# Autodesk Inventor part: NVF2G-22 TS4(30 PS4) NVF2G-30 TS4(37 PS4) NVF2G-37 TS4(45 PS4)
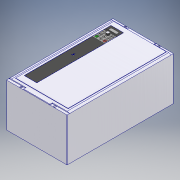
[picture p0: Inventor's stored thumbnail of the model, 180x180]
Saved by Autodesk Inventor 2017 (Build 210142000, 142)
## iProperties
Part Number: NVF2G-22 TS4(30 PS4) NVF2G-30 TS4(37 PS4) NVF2G-37 TS4(45 PS4)
Material: Типовые
Document SubType Name: Modeling
Designer: RSagdiev
Density: 1 g/cm^3
Appearance: По умолчанию
Author: RSagdiev
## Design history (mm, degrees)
sketch "Эскиз1"
  geometry: L1 (0, 0)-(44.679, 0) reference; L2 (0, 0)-(0, 56.035) reference; L3 (0, 0)-(527, 0); L4 (527, 0)-(527, 214.6); L5 (527, 214.6)-(0, 214.6); L6 (0, 214.6)-(0, 0)
  constraints: 12 end point, 3 horizontal, 2 parallel, 2 vertical, 1 perpendicular
  dimensions: "d0" = 527 distance of L5.end L4.end; "d1" = 214.6 distance of L4.end L3.end
extrude "Выдавливание1" new body sketch "Эскиз1" stored distance "d2" = 300; taper "d3" = 0 deg
sketch "Эскиз2"
  geometry: L1 (0, 0)-(0, 527) reference; L2 (300, 0)-(300, 527) reference; L3 (0, 527)-(85, 527); L4 (300, 527)-(300, 515); L5 (300, 0)-(215, 0); L6 (0, 0)-(0, 12); L7 (0, 527)-(300, 527) reference; L8 (0, 527)-(85, 527); L9 (85, 527)-(85, 515); L10 (85, 515)-(0, 515); L11 (0, 515)-(0, 527); L12 (300, 527)-(215, 527); L13 (215, 527)-(215, 515); L14 (215, 515)-(300, 515); L15 (300, 515)-(300, 527); L16 (0, 0)-(300, 0) reference; L17 (0, 0)-(85, 0); L18 (85, 0)-(85, 12); L19 (85, 12)-(0, 12); L20 (0, 12)-(0, 0); L21 (300, 0)-(215, 0); L22 (215, 0)-(215, 12); L23 (215, 12)-(300, 12); L24 (300, 12)-(300, 0); L25 (85, 527)-(215, 527); L26 (0, 515)-(0, 527); L27 (215, 527)-(300, 527); L28 (300, 515)-(300, 12); L29 (215, 0)-(85, 0); L30 (300, 12)-(300, 0); L31 (85, 0)-(0, 0); L32 (0, 12)-(0, 515); 1 further point
  constraints: 56 end point, 26 parallel, 13 perpendicular, 7 horizontal
  dimensions: "d4" = 85 distance of L9.end L10.end; "d5" = 12 distance of L3.end L9.end; "d6" = 85 distance of L4.end L13.end; "d7" = 12 distance of L13.end L12.end; "d8" = 85 distance of L6.end L18.end; "d9" = 12 distance of L18.end L17.end; "d10" = 85 distance of L22.end L23.end; "d11" = 12 distance of L5.end L22.end
extrude "Выдавливание2" new body sketch "Эскиз2" distance "d12" = 4; taper "d13" = 0 deg
chamfer "Фаска1" distance "d14" = 4; stored, may be unused: second distance "d15" = 2, angle "d16" = 45 deg
sketch "Эскиз3"
  geometry: L1 (280, 25)-(280, 511); L2 (20, 511)-(280, 511); L3 (20, 511)-(20, 25); L4 (20, 511)-(280, 511); L5 (20, 25)-(280, 25); L6 (85, 523)-(215, 523) reference; L7 (85, 0)-(215, 0) reference; L8 (0, 515)-(0, 12) reference; L9 (300, 12)-(300, 515) reference; 1 further point
  constraints: 11 end point, 2 perpendicular, 1 horizontal
  dimensions: "d160" = 12 distance between parallel lines of L4 L6; "d161" = 25 distance between parallel lines of L7 L5; "d162" = 20 distance between parallel lines of L8 L3 (derived); "d164" = 20 distance between parallel lines of L9 L1
extrude "Выдавливание3" new body sketch "Эскиз3" distance "d17" = 2; taper "d18" = 0 deg
sketch "Эскиз4"
  geometry: L1 (91, 487)-(32, 487); L2 (30, 485)-(30, 59); L3 (32, 57)-(91, 57); L4 (93, 59)-(93, 485); L5 (0, 527)-(300, 527) reference; L6 (0, 515)-(0, 12) reference; A1 r 2 centre (32, 485) between (32, 487) and (30, 485); A2 r 2 centre (91, 485) between (93, 485) and (91, 487); A3 r 2 centre (91, 59) between (91, 57) and (93, 59); A4 r 2 centre (32, 59) between (30, 59) and (32, 57); 6 further points
  constraints: 8 end point, 8 point on circle, 8 tangent, 6 point on line, 4 centre point, 3 equal radius, 2 parallel, 1 horizontal, 1 perpendicular
  dimensions: "d20" = 63 distance of point (93, 57) point (30, 57); "d21" = 430 distance of point (30, 57) point (30, 487); "d24" = 2 radius of A1; "d165" = 40 distance between parallel lines of L5 L1; "d166" = 30 distance between parallel lines of L6 L2
extrude "Выдавливание4" cut sketch "Эскиз4" distance "d25" = 0.6; taper "d26" = 0 deg
sketch "Эскиз5"
  geometry: L1 (0, 527)-(300, 527) reference; L2 (0, 0)-(0, 527) reference; L3 (300, 527)-(300, 0) reference; L4 (0, 0)-(300, 0) reference; C1 r 5 at (66.7, 521); C2 r 5 at (233.3, 521); C3 r 5 at (66.7, 6); C4 r 5 at (233.3, 6); 1 further point
  constraints: 4 centre point
  dimensions: "d27" = 10 diameter of C1; "d28" = 6 distance from line of C1.centre L1; "d30" = 10 diameter of C2; "d31" = 6 distance from line of C2.centre L1; "d33" = 10 diameter of C3; "d34" = 6 distance from line of L4 C3.centre; "d36" = 10 diameter of C4; "d38" = 6 distance from line of C4.centre L4; "d169" = 166.6 distance of C1.centre C2.centre; "d170" = 66.7 distance from line of L3 C2.centre; "d172" = 166.6 distance of C4.centre C3.centre (derived); "d173" = 66.7 distance from line of L3 C4.centre (derived); "d202" = 66.7 distance from line of L2 C1.centre (derived)
extrude "Выдавливание5" cut sketch "Эскиз5" stored distance "d39" = 0.6; taper "d40" = 0 deg
sketch "Эскиз6"
  geometry: L1 (30, 396)-(30, 452); L2 (91, 394)-(32, 394); L3 (93, 485)-(93, 452); L4 (32, 487)-(91, 487); L5 (30, 396)-(30, 485); L6 (30, 452)-(93, 452); L7 (93, 485)-(93, 452); L8 (30, 452)-(30, 485); L9 (93, 452)-(93, 396); L10 (43.5, 463)-(79.5, 463); L11 (81.5, 465)-(81.5, 475); L12 (79.5, 477)-(43.5, 477); L13 (41.5, 475)-(41.5, 465); L14 (41.5, 463)-(81.5, 477); L15 (81.5, 463)-(41.5, 477); L16 (61.5, 440.5)-(61.5, 405.857); L17 (53.25, 440.5)-(53.25, 405.857); L18 (69.75, 405.857)-(69.75, 440.5); L19 (47, 447)-(36, 447); L20 (35, 446)-(35, 435); L21 (36, 434)-(47, 434); L22 (48, 435)-(48, 446); L23 (48, 447)-(35, 434); L24 (35, 447)-(48, 434); L25 (81.5, 465)-(81.5, 400.5); L26 (41.5, 440.5)-(88.409, 440.5); L27 (39.654, 423.179)-(85.729, 423.179); L28 (39.654, 405.857)-(84.963, 405.857); L29 (88, 435)-(88, 446); L30 (76, 434)-(87, 434); L31 (88, 447)-(75, 434); L32 (75, 447)-(88, 434); L33 (75, 446)-(75, 435); L34 (87, 447)-(76, 447); L35 (88, 417.679)-(88, 428.679); L36 (76, 416.679)-(87, 416.679); L37 (88, 429.679)-(75, 416.679); L38 (75, 429.679)-(88, 416.679); L39 (75, 428.679)-(75, 417.679); L40 (87, 429.679)-(76, 429.679); L41 (88, 400.357)-(88, 411.357); L42 (76, 399.357)-(87, 399.357); L43 (88, 412.357)-(75, 399.357); L44 (75, 412.357)-(88, 399.357); L45 (75, 411.357)-(75, 400.357); L46 (87, 412.357)-(76, 412.357); L47 (48, 400.357)-(48, 411.357); L48 (36, 399.357)-(47, 399.357); L49 (48, 412.357)-(35, 399.357); L50 (35, 412.357)-(48, 399.357); L51 (35, 411.357)-(35, 400.357); L52 (47, 412.357)-(36, 412.357); L53 (48, 417.679)-(48, 428.679); L54 (36, 416.679)-(47, 416.679); L55 (48, 429.679)-(35, 416.679); L56 (35, 429.679)-(48, 416.679); L57 (35, 428.679)-(35, 417.679); L58 (47, 429.679)-(36, 429.679); L59 (91, 394)-(32, 394); L60 (0, 527)-(300, 527) reference; L61 (0, 513)-(0, 14); L62 (93, 452)-(93, 396); C1 r 6.5 at (61.5, 440.5); C2 r 6.5 at (61.5, 405.857); C3 r 6.5 at (61.5, 423.179); A1 r 2 centre (43.5, 475) between (43.5, 477) and (41.5, 475); A2 r 2 centre (79.5, 475) between (81.5, 475) and (79.5, 477); A3 r 2 centre (79.5, 465) between (79.5, 463) and (81.5, 465); A4 r 2 centre (43.5, 465) between (41.5, 465) and (43.5, 463); A5 r 8.25 centre (61.5, 440.5) between (69.75, 440.5) and (53.25, 440.5); A6 r 8.25 centre (61.5, 405.857) between (53.25, 405.857) and (69.75, 405.857); A7 r 1 centre (47, 446) between (48, 446) and (47, 447); A8 r 1 centre (47, 435) between (47, 434) and (48, 435); A9 r 1 centre (36, 435) between (35, 435) and (36, 434); A10 r 1 centre (36, 446) between (36, 447) and (35, 446); A11 r 1 centre (87, 435) between (87, 434) and (88, 435); A12 r 1 centre (87, 446) between (88, 446) and (87, 447); A13 r 1 centre (76, 446) between (76, 447) and (75, 446); A14 r 1 centre (76, 435) between (75, 435) and (76, 434); A15 r 1 centre (87, 417.679) between (87, 416.679) and (88, 417.679); A16 r 1 centre (87, 428.679) between (88, 428.679) and (87, 429.679); A17 r 1 centre (76, 428.679) between (76, 429.679) and (75, 428.679); A18 r 1 centre (76, 417.679) between (75, 417.679) and (76, 416.679); A19 r 1 centre (87, 400.357) between (87, 399.357) and (88, 400.357); A20 r 1 centre (87, 411.357) between (88, 411.357) and (87, 412.357); A21 r 1 centre (76, 411.357) between (76, 412.357) and (75, 411.357); A22 r 1 centre (76, 400.357) between (75, 400.357) and (76, 399.357); A23 r 1 centre (47, 400.357) between (47, 399.357) and (48, 400.357); A24 r 1 centre (47, 411.357) between (48, 411.357) and (47, 412.357); A25 r 1 centre (36, 411.357) between (36, 412.357) and (35, 411.357); A26 r 1 centre (36, 400.357) between (35, 400.357) and (36, 399.357); A27 r 1 centre (47, 417.679) between (47, 416.679) and (48, 417.679); A28 r 1 centre (47, 428.679) between (48, 428.679) and (47, 429.679); A29 r 1 centre (36, 428.679) between (36, 429.679) and (35, 428.679); A30 r 1 centre (36, 417.679) between (35, 417.679) and (36, 416.679); A31 r 2 centre (32, 485) between (32, 487) and (30, 485); A32 r 2 centre (91, 485) between (93, 485) and (91, 487); A33 r 2 centre (91, 396) between (91, 394) and (93, 396); A34 r 2 centre (32, 396) between (30, 396) and (32, 394); 15 further points
  constraints: 124 end point, 70 tangent, 68 point on circle, 67 point on line, 37 centre point, 21 equal radius, 15 midpoint, 15 parallel, 11 horizontal, 7 collinear, 7 perpendicular, 3 coincident, 2 vertical
  dimensions: "d43" = 35 distance between parallel lines of L4 L6; "d44" = 40 distance of L15.end L14.end; "d45" = 14 distance of L14.end L15.start; "d46" = 10 distance between parallel lines of L4 L12; "d47" = 2 radius of A1; "d48" = 11.5 distance between parallel lines of L8 L13; "d49" = 16.5 diameter of A6; "d50" = 31.5 distance between parallel lines of L1 L16; "d51" = 11.5 distance from line of L6 L16.start; "d52" = 11.85714 distance from line of L2 L16.end; "d53" = 13 diameter of C1; "d54" = 13 diameter of C2; "d55" = 13 diameter of C3; "d56" = 13 distance of L24.end L23.end; "d57" = 13 distance of L23.end L24.start; "d58" = 1 radius of A7 (derived); "d59" = 11.5 distance from line of L6 L26.start; "d60" = 11.5 distance from line of L5 L26.start; "d61" = 13 distance of L32.end L31.end; "d62" = 13 distance of L31.end L32.start; "d63" = 1 radius of A12 (derived); "d64" = 13 distance of L38.end L37.end; "d65" = 13 distance of L37.end L38.start; "d66" = 1 radius of A16 (derived); "d67" = 13 distance of L44.end L43.end; "d68" = 13 distance of L43.end L44.start; "d69" = 1 radius of A20 (derived); "d70" = 13 distance of L50.end L49.end; "d71" = 13 distance of L49.end L50.start; "d72" = 1 radius of A24 (derived); "d73" = 13 distance of L56.end L55.end; "d74" = 13 distance of L55.end L56.start; "d75" = 1 radius of A28 (derived); "d146" = 40 distance of point (81.5, 440.5) L26.start; "d147" = 4.32143 distance between parallel lines of L40 L30; "d148" = 4.32143 distance between parallel lines of L46 L36; "d149" = 93 distance between parallel lines of L2 L4; "d151" = 2 radius of A31; "d152" = 2 radius of A32; "d153" = 2 radius of A33; "d154" = 2 radius of A34; "d167" = 40 distance between parallel lines of L4 L60 (derived); "d168" = 30 distance between parallel lines of L61 L5 (derived)
extrude "Выдавливание6" new body sketch "Эскиз6" distance "d76" = 0.3; taper "d77" = 0 deg
extrude "Выдавливание7" new body sketch "Эскиз6" distance "d78" = 0.6; taper "d79" = 0 deg
sketch "Эскиз7"
  geometry: L1 (30, 452)-(93, 452) reference; L2 (30, 452)-(93, 452); L3 (93, 452)-(93, 452.1); L4 (93, 452.1)-(30, 452.1); L5 (30, 452.1)-(30, 452); 4 further points; 1 other entity
  constraints: 8 end point, 2 parallel, 1 horizontal, 1 perpendicular, 2 other
  dimensions: "d80" = 0.1 distance of L3.end L2.end
extrude "Выдавливание8" cut sketch "Эскиз7" distance "d81" = 0.3; taper "d82" = 0 deg
sketch "Эскиз8" dims "d91" = 10
  geometry: L1 (30, 452.1)-(93, 452.1) reference; C1 r 1 at (38, 457.1); C2 r 1 at (45.75, 457.1); C3 r 1 at (53.5, 457.1); C4 r 1 at (61.25, 457.1); C5 r 1 at (69, 457.1); C6 r 1 at (76.75, 457.1); C7 r 1 at (84.5, 457.1); 4 further points; 1 other entity
  constraints: 7 centre point, 1 horizontal, 13 other
  dimensions: "d83" = 2 diameter of C1; "d84" = 5 distance from line of C1.centre L1; "d85" = 8 dimension on C1.centre; "d88" = 7.75 distance of C1.centre C2.centre
extrude "Выдавливание9" join sketch "Эскиз8" distance "d93" = 0.3; taper "d94" = 0 deg
sketch "Эскиз9"
  geometry: C1 r 6.5 at (0, 0) reference; C2 r 7.5 at (0, 0); 1 further point
  constraints: 1 centre point, 1 coincident
  dimensions: "d95" = 15 diameter of C2
extrude "Выдавливание10" join sketch "Эскиз9" distance "d96" = 9.4; taper "d97" = -3 deg
sketch "Эскиз10"
  geometry: L1 (0, 7.331)-(0.619, 6.259); L2 (0.619, 6.259)-(-0.619, 6.259); L3 (-0.619, 6.259)-(0, 7.331); 2 further points
  constraints: 6 end point, 7 other
sketch "Эскиз11"
  geometry: L1 (0, 7.917)-(0.884, 6.386); L2 (0.884, 6.386)-(-0.884, 6.386); L3 (-0.884, 6.386)-(0, 7.917); 2 further points
  constraints: 6 end point, 7 other
feature "Лофт1" sketch "Эскиз10", "Эскиз11" dims "d98" = 0, "d99" = 90 deg, "d100" = 0, "d101" = 90 deg
sketch "Эскиз12"
  geometry: L1 (38.019, 442.615)-(44.239, 442.615); L2 (44.239, 442.615)-(44.239, 439.115); L3 (44.239, 439.115)-(38.019, 439.115); L4 (38.019, 439.115)-(38.019, 442.615); L5 (37.069, 425.516)-(45.924, 425.516); L6 (45.924, 425.516)-(45.924, 421.886); L7 (45.924, 421.886)-(37.069, 421.886); L8 (37.069, 421.886)-(37.069, 425.516); L9 (36.713, 408.18)-(46.07, 408.18); L10 (46.07, 408.18)-(46.07, 404.606); L11 (46.07, 404.606)-(36.713, 404.606); L12 (36.713, 404.606)-(36.713, 408.18); L13 (75.542, 408.18)-(87.094, 408.18); L14 (87.094, 408.18)-(87.094, 404.533); L15 (87.094, 404.533)-(75.542, 404.533); L16 (75.542, 404.533)-(75.542, 408.18); L17 (77.323, 425.398)-(85.517, 425.398); L18 (85.517, 425.398)-(85.517, 421.773); L19 (85.517, 421.773)-(77.323, 421.773); L20 (77.323, 421.773)-(77.323, 425.398); L21 (75.423, 442.734)-(88.473, 442.734); L22 (88.473, 442.734)-(88.473, 439.109); L23 (88.473, 439.109)-(75.423, 439.109); L24 (75.423, 439.109)-(75.423, 442.734); 1 further point
  constraints: 12 other
feature "Рельеф1" dims "d105" = 0.1, "d106" = 0
feature "Рельеф2" dims "d107" = 0.1, "d108" = 0
feature "Рельеф3" dims "d109" = 0.1, "d110" = 0
feature "Рельеф4" dims "d111" = 0.1, "d112" = 0
feature "Рельеф5" dims "d113" = 0.1, "d114" = 0
feature "Рельеф6" dims "d115" = 0.1, "d116" = 0
sketch "Эскиз13"
  geometry: L1 (-3.144, -2.347)-(-0.04, 3.728); L2 (-0.04, 3.728)-(3.298, -2.347); L3 (3.298, -2.347)-(2.096, -2.347); L4 (2.096, -2.347)-(-0.04, 1.541); L5 (-0.04, 1.541)-(-2.027, -2.347); L6 (-2.027, -2.347)-(-3.144, -2.347); L7 (-9.387, -8.657)-(8.031, -8.657); L8 (-3.144, -14.967)-(-0.04, -21.041); L9 (-0.04, -21.041)-(3.298, -14.967); L10 (3.298, -14.967)-(2.096, -14.967); L11 (2.096, -14.967)-(-0.04, -18.855); L12 (-0.04, -18.855)-(-2.027, -14.967); L13 (-2.027, -14.967)-(-3.144, -14.967); 1 further point
  constraints: 26 end point, 6 symmetric about line, 2 horizontal, 2 parallel, 2 point on line, 1 collinear
feature "Рельеф7" dims "d117" = 0.1, "d118" = 0
feature "Рельеф8" dims "d119" = 0.1, "d120" = 0
sketch "Эскиз14"
  geometry: L1 (62.079, 278.98)-(70.375, 264.61); L2 (70.375, 264.61)-(53.782, 264.61); L3 (53.782, 264.61)-(62.079, 278.98); L4 (68.948, 265.434)-(62.079, 277.332); L5 (62.079, 277.332)-(55.209, 265.434); L6 (55.209, 265.434)-(68.948, 265.434); L7 (61.252, 273.665)-(60.311, 269.855); L8 (60.311, 269.855)-(62.732, 270.025); L9 (62.732, 270.025)-(61.691, 267.709); L10 (61.691, 267.709)-(60.742, 268.135); L11 (60.742, 268.135)-(60.898, 265.905); L12 (60.898, 265.905)-(63.368, 266.954); L13 (63.368, 266.954)-(62.687, 267.261); L14 (62.687, 267.261)-(64.617, 270.896); L15 (64.617, 270.896)-(61.462, 270.713); L16 (61.462, 270.713)-(63.028, 273.665); L17 (63.028, 273.665)-(61.252, 273.665); 2 further points
  constraints: 34 end point, 2 perpendicular, 2 point on line, 1 parallel, 9 other
extrude "Выдавливание11" cut sketch "Эскиз14" distance "d121" = 0.8; taper "d122" = 0 deg
extrude "Выдавливание12" join sketch "Эскиз14" stored distance "d123" = 0.05; taper "d124" = 0 deg
sketch "Эскиз15"
  geometry: L1 (32.937, 461.659)-(59.334, 461.659); L2 (59.334, 461.659)-(59.334, 458.81); L3 (59.334, 458.81)-(32.937, 458.81); L4 (32.937, 458.81)-(32.937, 461.659); L5 (58.162, 460.617)-(88.881, 460.617); L6 (88.881, 460.617)-(88.881, 456.704); L7 (88.881, 456.704)-(58.162, 456.704); L8 (58.162, 456.704)-(58.162, 460.617); L9 (30, 452.1)-(93, 452.1) reference; C1 r 1 at (38, 457.1) reference; 7 further points; 2 other entities
  constraints: 6 other
  dimensions: "d155" = 0.71019 distance edge to line of C1 L3; "d156" = 2.93695 dimension on L4; "d157" = 4.60387 distance between parallel lines of L9 L7; "d158" = 4.11868 dimension on L6
feature "Рельеф9" sketch "Эскиз15" dims "d125" = 0.1, "d126" = 0
sketch "Эскиз17"
  geometry: L1 (54.534, 359)-(54.534, 352.001); L2 (54.534, 352.001)-(52.465, 352.001); L3 (52.465, 352.001)-(52.465, 359); L4 (52.465, 359)-(54.534, 359); 1 further point
  constraints: 2 other
feature "Рельеф10" sketch "Эскиз17" dims "d144" = 0.1, "d145" = 0
sketch "Эскиз19" dims "d179" = 10
  geometry: L1 (113.24, 333.958)-(134.375, 351.485); L2 (114.525, 332.409)-(135.66, 349.935); L3 (133.09, 353.034)-(111.955, 335.508); L4 (214.6, 515)-(214.6, 12) reference; L5 (113.24, 323.958)-(134.375, 341.485); L6 (114.525, 322.409)-(135.66, 339.935); L7 (133.09, 343.034)-(111.955, 325.508); L8 (113.24, 313.958)-(134.375, 331.485); L9 (114.525, 312.409)-(135.66, 329.935); L10 (133.09, 333.034)-(111.955, 315.508); L11 (113.24, 303.958)-(134.375, 321.485); L12 (114.525, 302.409)-(135.66, 319.935); L13 (133.09, 323.034)-(111.955, 305.508); L14 (113.24, 293.958)-(134.375, 311.485); L15 (114.525, 292.409)-(135.66, 309.935); L16 (133.09, 313.034)-(111.955, 295.508); L17 (113.24, 283.958)-(134.375, 301.485); L18 (114.525, 282.409)-(135.66, 299.935); L19 (133.09, 303.034)-(111.955, 285.508); L20 (113.24, 273.958)-(134.375, 291.485); L21 (114.525, 272.409)-(135.66, 289.935); L22 (133.09, 293.034)-(111.955, 275.508); L23 (113.24, 263.958)-(134.375, 281.485); L24 (114.525, 262.409)-(135.66, 279.935); L25 (133.09, 283.034)-(111.955, 265.508); L26 (113.24, 253.958)-(134.375, 271.485); L27 (114.525, 252.409)-(135.66, 269.935); L28 (133.09, 273.034)-(111.955, 255.508); L29 (113.24, 243.958)-(134.375, 261.485); L30 (114.525, 242.409)-(135.66, 259.935); L31 (133.09, 263.034)-(111.955, 245.508); A1 r 2.013 centre (113.24, 333.958) between (111.955, 335.508) and (114.525, 332.409); A2 r 2.013 centre (134.375, 351.485) between (135.66, 349.935) and (133.09, 353.034); A3 r 2.013 centre (113.24, 323.958) between (111.955, 325.508) and (114.525, 322.409); A4 r 2.013 centre (134.375, 341.485) between (135.66, 339.935) and (133.09, 343.034); A5 r 2.013 centre (113.24, 313.958) between (111.955, 315.508) and (114.525, 312.409); A6 r 2.013 centre (134.375, 331.485) between (135.66, 329.935) and (133.09, 333.034); A7 r 2.013 centre (113.24, 303.958) between (111.955, 305.508) and (114.525, 302.409); A8 r 2.013 centre (134.375, 321.485) between (135.66, 319.935) and (133.09, 323.034); A9 r 2.013 centre (113.24, 293.958) between (111.955, 295.508) and (114.525, 292.409); A10 r 2.013 centre (134.375, 311.485) between (135.66, 309.935) and (133.09, 313.034); A11 r 2.013 centre (113.24, 283.958) between (111.955, 285.508) and (114.525, 282.409); A12 r 2.013 centre (134.375, 301.485) between (135.66, 299.935) and (133.09, 303.034); A13 r 2.013 centre (113.24, 273.958) between (111.955, 275.508) and (114.525, 272.409); A14 r 2.013 centre (134.375, 291.485) between (135.66, 289.935) and (133.09, 293.034); A15 r 2.013 centre (113.24, 263.958) between (111.955, 265.508) and (114.525, 262.409); A16 r 2.013 centre (134.375, 281.485) between (135.66, 279.935) and (133.09, 283.034); A17 r 2.013 centre (113.24, 253.958) between (111.955, 255.508) and (114.525, 252.409); A18 r 2.013 centre (134.375, 271.485) between (135.66, 269.935) and (133.09, 273.034); A19 r 2.013 centre (113.24, 243.958) between (111.955, 245.508) and (114.525, 242.409); A20 r 2.013 centre (134.375, 261.485) between (135.66, 259.935) and (133.09, 263.034); 13 further points
  constraints: 80 end point, 40 point on circle, 20 centre point, 4 tangent, 1 midpoint, 1 parallel, 1 vertical, 108 other
  dimensions: "d176" = 10 distance of L2.start L6.start
extrude "Выдавливание14" cut sketch "Эскиз19" distance "d181" = 10; taper "d182" = 0 deg
sketch "Эскиз20" dims "d191" = 10, "d198" = 10
  geometry: L1 (214.6, 2)-(0, 2) reference; L2 (0, 527)-(0, 0) reference; C1 r 2 at (15, 132); C2 r 2 at (20, 132); C3 r 2 at (25, 132); C4 r 2 at (30, 132); C5 r 2 at (35, 132); C6 r 2 at (40, 132); C7 r 2 at (45, 132); C8 r 2 at (50, 132); C9 r 2 at (55, 132); C10 r 2 at (60, 132); C11 r 2 at (65, 132); C12 r 2 at (70, 132); C13 r 2 at (70, 127); C14 r 2 at (65, 127); C15 r 2 at (60, 127); C16 r 2 at (55, 127); C17 r 2 at (15, 127); C18 r 2 at (20, 127); C19 r 2 at (25, 127); C20 r 2 at (30, 127); C21 r 2 at (35, 127); C22 r 2 at (40, 127); C23 r 2 at (45, 127); C24 r 2 at (50, 127); C25 r 2 at (70, 122); C26 r 2 at (65, 122); C27 r 2 at (60, 122); C28 r 2 at (55, 122); C29 r 2 at (15, 122); C30 r 2 at (20, 122); C31 r 2 at (25, 122); C32 r 2 at (30, 122); C33 r 2 at (35, 122); C34 r 2 at (40, 122); C35 r 2 at (45, 122); C36 r 2 at (50, 122); C37 r 2 at (70, 117); C38 r 2 at (65, 117); C39 r 2 at (60, 117); C40 r 2 at (55, 117); C41 r 2 at (15, 117); C42 r 2 at (20, 117); C43 r 2 at (25, 117); C44 r 2 at (30, 117); C45 r 2 at (35, 117); C46 r 2 at (40, 117); C47 r 2 at (45, 117); C48 r 2 at (50, 117); C49 r 2 at (70, 112); C50 r 2 at (65, 112); C51 r 2 at (60, 112); C52 r 2 at (55, 112); C53 r 2 at (15, 112); C54 r 2 at (20, 112); C55 r 2 at (25, 112); C56 r 2 at (30, 112); C57 r 2 at (35, 112); C58 r 2 at (40, 112); C59 r 2 at (45, 112); C60 r 2 at (50, 112); C61 r 2 at (70, 107); C62 r 2 at (65, 107); C63 r 2 at (60, 107); C64 r 2 at (55, 107)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; 1 further point
  constraints: 240 centre point, 1 horizontal, 1 vertical, 478 other
  dimensions: "d183" = 4 diameter of C1; "d184" = 15 distance from line of L2 C1.centre; "d185" = 130 distance from line of L1 C1.centre; "d188" = 5 distance of C1.centre C2.centre; "d195" = 5 distance of C12.centre C13.centre
extrude "Выдавливание15" cut sketch "Эскиз20" distance "d200" = 15; taper "d201" = 0 deg
fillet "Сопряжение3" dims "d203" = 20
fillet "Сопряжение4" dims "d204" = 2
node "Твердое тело1"
pattern_circular "Круговой массив1" dims angle "d103" = 360 deg
node "Твердое тело2"
node "Твердое тело3"
node "Твердое тело4"
node "Твердое тело5"
feature "䀀䁈"
